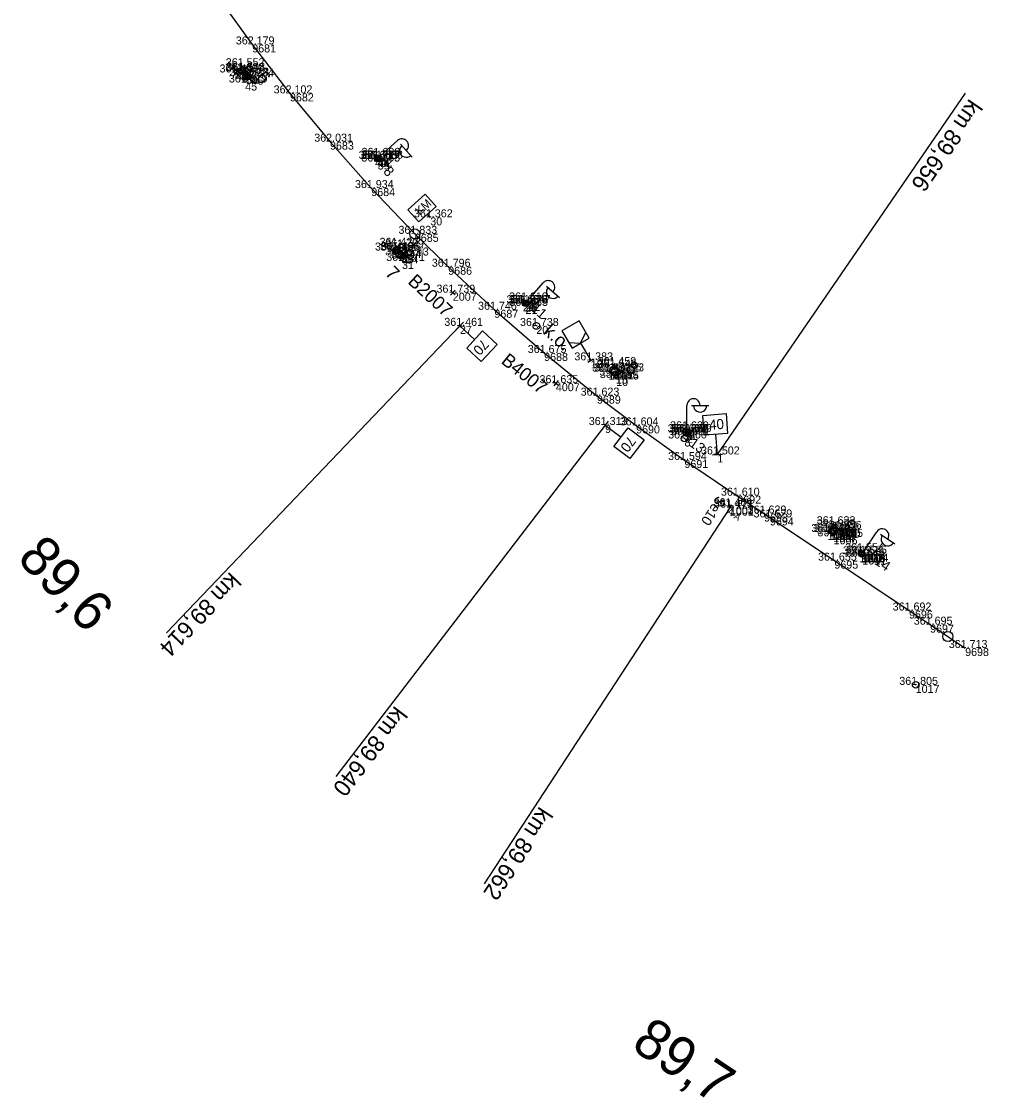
# Model space of a CAD drawing. Extents: x -599511 to -595511, y -1067427 to -1062061.
# Drawn here: x -595656.1 to -595511.1, y -1067426.6 to -1067265.2 of the extents above; entities that cross this region are included whole.
import ezdxf

# ---------------------------------------------------------------- set-up
doc = ezdxf.new("R2010")
doc.units = 0
for name, color, linetype in [('Vrstva 1', 7, 'Continuous'), ('Vrstva 11', 7, 'Continuous'), ('Vrstva 12', 7, 'Continuous'), ('Vrstva 23', 7, 'Continuous'), ('Vrstva 25', 7, 'Continuous'), ('Vrstva 27', 7, 'Continuous'), ('Vrstva 49', 7, 'Continuous'), ('Vrstva 5', 7, 'Continuous'), ('Vrstva 50', 7, 'Continuous'), ('Vrstva 6', 7, 'Continuous'), ('Vrstva 60', 7, 'Continuous'), ('Vrstva 61', 7, 'Continuous'), ('Vrstva 7', 7, 'Continuous')]:
    doc.layers.add(name, color=color, linetype=linetype)

msp = doc.modelspace()

# ---------------------------------------------------------------- linework, layer by layer
at = {"layer": 'Vrstva 1'}
msp.add_lwpolyline([(-595627.48, -1067260.3), (-595621.49, -1067268.64), (-595615.83, -1067275.98), (-595609.83, -1067283.22), (-595603.64, -1067290.18), (-595597.11, -1067297.04), (-595592.1, -1067301.98), (-595585.18, -1067308.43), (-595577.72, -1067314.91), (-595569.8, -1067321.31), (-595563.93, -1067325.77), (-595556.69, -1067330.96), (-595548.76, -1067336.31), (-595544.74, -1067338.99), (-595543.87, -1067339.57), (-595534.2, -1067346.05), (-595523.01, -1067353.53), (-595519.85, -1067355.65), (-595514.6, -1067359.15)], dxfattribs=at)
at = {"layer": 'Vrstva 11'}
for p, q in [((-595623.57, -1067272.76), (-595622.65, -1067272.87)), ((-595623.52, -1067272.39), (-595622.61, -1067272.5)), ((-595622.94, -1067273.51), (-595622.02, -1067273.63)), ((-595622.88, -1067273.14), (-595621.97, -1067273.26)), ((-595600.28, -1067299.72), (-595599.36, -1067299.74)), ((-595600.27, -1067299.35), (-595599.35, -1067299.37)), ((-595599.56, -1067300.08), (-595598.65, -1067300.07)), ((-595599.57, -1067300.45), (-595598.64, -1067300.45)), ((-595567.8, -1067317.77), (-595566.41, -1067317.58)), ((-595567.48, -1067317.35), (-595566.83, -1067317.26)), ((-595567.39, -1067318.09), (-595566.72, -1067318)), ((-595535.07, -1067341.7), (-595533.68, -1067341.43)), ((-595534.77, -1067341.26), (-595534.12, -1067341.14)), ((-595534.63, -1067342), (-595533.97, -1067341.87))]:
    msp.add_line(p, q, dxfattribs=at)
for points in [[(-595567.2, -1067316.97), (-595566.4, -1067317.58), (-595567.01, -1067318.38), (-595567.8, -1067317.77)], [(-595534.51, -1067340.88), (-595533.68, -1067341.43), (-595534.24, -1067342.26), (-595535.07, -1067341.71)]]:
    msp.add_lwpolyline(points, close=True, dxfattribs=at)
for centre in [(-595623.09, -1067272.64), (-595622.45, -1067273.39), (-595599.82, -1067299.55), (-595599.11, -1067300.27)]:
    msp.add_circle(centre, 0.5, dxfattribs=at)
at = {"layer": 'Vrstva 12'}
for p, q in [((-595535.21, -1067341.75), (-595534.4, -1067340.59)), ((-595534.31, -1067342.4), (-595535.21, -1067341.75)), ((-595534.4, -1067340.59), (-595533.48, -1067341.29)), ((-595533.48, -1067341.29), (-595534.31, -1067342.4)), ((-595530.47, -1067345.1), (-595530.14, -1067344.64)), ((-595530.01, -1067345.44), (-595530.47, -1067345.1)), ((-595530.14, -1067344.64), (-595529.69, -1067345.01)), ((-595529.69, -1067345.01), (-595530.01, -1067345.44))]:
    msp.add_line(p, q, dxfattribs=at)
for points in [[(-595623.94, -1067272.84), (-595623.01, -1067271.91), (-595621.6, -1067273.48), (-595622.55, -1067274.35)], [(-595602.65, -1067285.35), (-595603.08, -1067285.8), (-595602.67, -1067286.2), (-595602.26, -1067285.76)], [(-595600.63, -1067299.55), (-595599.94, -1067298.84), (-595598.38, -1067300.29), (-595599.04, -1067301.11)], [(-595580.53, -1067307.03), (-595580.09, -1067307.41), (-595580.5, -1067307.85), (-595580.92, -1067307.45)], [(-595568.08, -1067317.7), (-595567.26, -1067316.71), (-595566.1, -1067317.65), (-595566.92, -1067318.67)], [(-595556.74, -1067326.79), (-595556.37, -1067326.36), (-595555.95, -1067326.76), (-595556.3, -1067327.17)]]:
    msp.add_lwpolyline(points, close=True, dxfattribs=at)
at = {"layer": 'Vrstva 23'}
for p, q in [((-595534.85, -1067341.74), (-595534.39, -1067341.06)), ((-595534.36, -1067342.07), (-595534.85, -1067341.74)), ((-595534.39, -1067341.06), (-595533.88, -1067341.39)), ((-595533.88, -1067341.39), (-595534.36, -1067342.07))]:
    msp.add_line(p, q, dxfattribs=at)
msp.add_lwpolyline([(-595567.22, -1067317.09), (-595566.45, -1067317.67), (-595566.98, -1067318.31), (-595567.73, -1067317.68)], close=True, dxfattribs=at)
at = {"layer": 'Vrstva 25'}
for p, q in [((-595602.32, -1067285.38), (-595599.71, -1067283.05)), ((-595599.24, -1067283.58), (-595597.52, -1067285.52)), ((-595603.12, -1067285.45), (-595602.25, -1067285.5)), ((-595603.18, -1067285.82), (-595602.23, -1067285.88)), ((-595580.18, -1067307.05), (-595577.89, -1067304.41)), ((-595577.36, -1067304.87), (-595575.4, -1067306.57)), ((-595580.98, -1067307.6), (-595580.02, -1067307.53)), ((-595580.97, -1067307.22), (-595580.09, -1067307.16)), ((-595556.35, -1067326.27), (-595556.33, -1067322.77)), ((-595555.63, -1067322.77), (-595553.03, -1067322.79)), ((-595556.83, -1067326.91), (-595556.21, -1067326.29)), ((-595556.6, -1067327.2), (-595555.92, -1067326.53)), ((-595529.81, -1067344.62), (-595527.86, -1067341.71)), ((-595527.28, -1067342.1), (-595525.12, -1067343.54)), ((-595530.56, -1067344.89), (-595529.7, -1067344.72)), ((-595530.53, -1067345.27), (-595529.59, -1067345.08))]:
    msp.add_line(p, q, dxfattribs=at)
for centre in [(-595602.7, -1067285.71), (-595580.51, -1067307.43), (-595556.35, -1067326.76), (-595530.08, -1067345.04)]:
    msp.add_circle(centre, 0.5, dxfattribs=at)
for centre, start, end in [((-595599.04, -1067283.8), 311.633, 131.633), ((-595598.39, -1067284.56), 130.9305, 312.3356), ((-595577.13, -1067305.06), 319.0231, 139.0231), ((-595576.39, -1067305.73), 138.3205, 319.7256), ((-595555.33, -1067322.77), 359.6536, 179.6536), ((-595554.33, -1067322.79), 178.951, 0.3562), ((-595527.03, -1067342.27), 326.2332, 146.2332), ((-595526.2, -1067342.83), 145.5306, 326.9358)]:
    msp.add_arc(centre, 1, start, end, dxfattribs=at)
at = {"layer": 'Vrstva 27'}
msp.add_line((-595578.93, -1067310.83), (-595578.85, -1067310.89), dxfattribs=at)
msp.add_circle((-595578.89, -1067310.86), 0.5, dxfattribs=at)
at = {"layer": 'Vrstva 49'}
for p, q in [((-595623.16, -1067272.54), (-595622.66, -1067272.6)), ((-595622.88, -1067272.32), (-595622.94, -1067272.82)), ((-595622.55, -1067273.3), (-595622.05, -1067273.37)), ((-595622.27, -1067273.09), (-595622.33, -1067273.58)), ((-595602.72, -1067285.57), (-595602.75, -1067286.07)), ((-595602.98, -1067285.8), (-595602.48, -1067285.83)), ((-595599.97, -1067299.46), (-595599.47, -1067299.46)), ((-595599.72, -1067299.21), (-595599.72, -1067299.71)), ((-595599.28, -1067300.16), (-595598.78, -1067300.16)), ((-595599.03, -1067299.91), (-595599.03, -1067300.41)), ((-595580.82, -1067307.53), (-595580.32, -1067307.5)), ((-595580.59, -1067307.26), (-595580.55, -1067307.76)), ((-595556.66, -1067326.89), (-595556.17, -1067326.81)), ((-595556.45, -1067326.6), (-595556.37, -1067327.09)), ((-595550.11, -1067337.93), (-595549.62, -1067337.84)), ((-595549.92, -1067337.64), (-595549.82, -1067338.13)), ((-595530.38, -1067345.18), (-595529.89, -1067345.08)), ((-595530.18, -1067344.88), (-595530.09, -1067345.37))]:
    msp.add_line(p, q, dxfattribs=at)
at = {"layer": 'Vrstva 5'}
for p, q in [((-595551.75, -1067330.12), (-595514.53, -1067275.94)), ((-595590.34, -1067310.84), (-595634.35, -1067356.9)), ((-595589.83, -1067310.29), (-595590.85, -1067311.39)), ((-595590.34, -1067310.84), (-595588.14, -1067312.89)), ((-595568.58, -1067325.71), (-595608.94, -1067378.44)), ((-595568.12, -1067325.12), (-595569.03, -1067326.31)), ((-595568.58, -1067325.71), (-595566.19, -1067327.53)), ((-595551.75, -1067330.12), (-595551.97, -1067327.12)), ((-595552.5, -1067330.17), (-595551, -1067330.06))]:
    msp.add_line(p, q, dxfattribs=at)
for points in [[(-595589.33, -1067314.17), (-595586.95, -1067311.61), (-595584.75, -1067313.65), (-595587.14, -1067316.21)], [(-595550.22, -1067327), (-595553.72, -1067327.25), (-595553.94, -1067324.26), (-595550.45, -1067324)], [(-595567.25, -1067328.92), (-595565.13, -1067326.14), (-595562.74, -1067327.95), (-595564.86, -1067330.74)]]:
    msp.add_lwpolyline(points, close=True, dxfattribs=at)
at = {"layer": 'Vrstva 50'}
msp.add_line((-595556.72, -1067327.7), (-595556.64, -1067327.76), dxfattribs=at)
msp.add_circle((-595556.68, -1067327.73), 0.5, dxfattribs=at)
at = {"layer": 'Vrstva 6'}
for p, q in [((-595549.87, -1067338.11), (-595586.71, -1067394.51)), ((-595550.15, -1067338.53), (-595549.59, -1067337.7))]:
    msp.add_line(p, q, dxfattribs=at)
at = {"layer": 'Vrstva 60'}
for p, q in [((-595621.49, -1067268.64), (-595621.49, -1067268.64)), ((-595623.09, -1067272.64), (-595623.09, -1067272.64)), ((-595623.01, -1067271.91), (-595623.01, -1067271.91)), ((-595622.91, -1067272.57), (-595622.91, -1067272.57)), ((-595623.94, -1067272.84), (-595623.94, -1067272.84)), ((-595622.55, -1067274.35), (-595622.55, -1067274.35)), ((-595622.45, -1067273.39), (-595622.45, -1067273.39)), ((-595622.3, -1067273.33), (-595622.3, -1067273.33)), ((-595621.6, -1067273.48), (-595621.6, -1067273.48)), ((-595615.83, -1067275.98), (-595615.83, -1067275.98)), ((-595609.83, -1067283.22), (-595609.83, -1067283.22)), ((-595602.7, -1067285.71), (-595602.7, -1067285.71)), ((-595602.65, -1067285.35), (-595602.65, -1067285.35)), ((-595603.08, -1067285.8), (-595603.08, -1067285.8)), ((-595602.73, -1067285.82), (-595602.73, -1067285.82)), ((-595602.67, -1067286.2), (-595602.67, -1067286.2)), ((-595602.26, -1067285.76), (-595602.26, -1067285.76)), ((-595603.64, -1067290.18), (-595603.64, -1067290.18)), ((-595594.79, -1067294.57), (-595594.79, -1067294.57)), ((-595597.11, -1067297.04), (-595597.11, -1067297.04)), ((-595600.63, -1067299.55), (-595600.63, -1067299.55)), ((-595599.94, -1067298.84), (-595599.94, -1067298.84)), ((-595599.82, -1067299.55), (-595599.82, -1067299.55)), ((-595599.72, -1067299.46), (-595599.72, -1067299.46)), ((-595599.11, -1067299.08), (-595599.11, -1067299.08)), ((-595599.03, -1067300.16), (-595599.03, -1067300.16)), ((-595599.11, -1067300.27), (-595599.11, -1067300.27)), ((-595599.04, -1067301.11), (-595599.04, -1067301.11)), ((-595598.38, -1067300.29), (-595598.38, -1067300.29)), ((-595592.1, -1067301.98), (-595592.1, -1067301.98)), ((-595591.41, -1067305.87), (-595591.41, -1067305.87)), ((-595580.92, -1067307.45), (-595580.92, -1067307.45)), ((-595580.57, -1067307.51), (-595580.57, -1067307.51)), ((-595580.53, -1067307.03), (-595580.53, -1067307.03)), ((-595580.51, -1067307.43), (-595580.51, -1067307.43)), ((-595580.5, -1067307.85), (-595580.5, -1067307.85)), ((-595580.09, -1067307.41), (-595580.09, -1067307.41)), ((-595585.18, -1067308.43), (-595585.18, -1067308.43)), ((-595590.34, -1067310.84), (-595590.34, -1067310.84)), ((-595578.89, -1067310.86), (-595578.89, -1067310.86)), ((-595577.72, -1067314.91), (-595577.72, -1067314.91)), ((-595570.74, -1067316.02), (-595570.74, -1067316.02)), ((-595568.08, -1067317.7), (-595568.08, -1067317.7)), ((-595567.73, -1067317.68), (-595567.73, -1067317.68)), ((-595567.26, -1067316.71), (-595567.26, -1067316.71)), ((-595567.22, -1067317.09), (-595567.22, -1067317.09)), ((-595567.1, -1067317.68), (-595567.1, -1067317.68)), ((-595566.45, -1067317.67), (-595566.45, -1067317.67)), ((-595566.1, -1067317.65), (-595566.1, -1067317.65)), ((-595575.96, -1067319.44), (-595575.96, -1067319.44)), ((-595566.98, -1067318.31), (-595566.98, -1067318.31)), ((-595566.92, -1067318.67), (-595566.92, -1067318.67)), ((-595569.8, -1067321.31), (-595569.8, -1067321.31)), ((-595568.58, -1067325.71), (-595568.58, -1067325.71)), ((-595563.93, -1067325.77), (-595563.93, -1067325.77)), ((-595556.74, -1067326.79), (-595556.74, -1067326.79)), ((-595556.41, -1067326.85), (-595556.41, -1067326.85)), ((-595556.37, -1067326.36), (-595556.37, -1067326.36)), ((-595556.35, -1067326.76), (-595556.35, -1067326.76)), ((-595556.3, -1067327.17), (-595556.3, -1067327.17)), ((-595555.95, -1067326.76), (-595555.95, -1067326.76)), ((-595556.68, -1067327.73), (-595556.68, -1067327.73)), ((-595551.75, -1067330.12), (-595551.75, -1067330.12)), ((-595556.69, -1067330.96), (-595556.69, -1067330.96)), ((-595548.76, -1067336.31), (-595548.76, -1067336.31)), ((-595549.87, -1067337.89), (-595549.87, -1067337.89)), ((-595549.87, -1067338.11), (-595549.87, -1067338.11)), ((-595544.74, -1067338.99), (-595544.74, -1067338.99)), ((-595543.87, -1067339.57), (-595543.87, -1067339.57)), ((-595535.21, -1067341.75), (-595535.21, -1067341.75)), ((-595534.85, -1067341.74), (-595534.85, -1067341.74)), ((-595534.4, -1067340.59), (-595534.4, -1067340.59)), ((-595534.39, -1067341.06), (-595534.39, -1067341.06)), ((-595534.37, -1067341.57), (-595534.37, -1067341.57)), ((-595534.36, -1067342.07), (-595534.36, -1067342.07)), ((-595533.88, -1067341.39), (-595533.88, -1067341.39)), ((-595533.48, -1067341.29), (-595533.48, -1067341.29)), ((-595534.31, -1067342.4), (-595534.31, -1067342.4)), ((-595530.47, -1067345.1), (-595530.47, -1067345.1)), ((-595530.14, -1067344.64), (-595530.14, -1067344.64)), ((-595530.14, -1067345.13), (-595530.14, -1067345.13)), ((-595530.08, -1067345.04), (-595530.08, -1067345.04)), ((-595529.69, -1067345.01), (-595529.69, -1067345.01)), ((-595534.2, -1067346.05), (-595534.2, -1067346.05)), ((-595530.01, -1067345.44), (-595530.01, -1067345.44)), ((-595523.01, -1067353.53), (-595523.01, -1067353.53)), ((-595519.85, -1067355.65), (-595519.85, -1067355.65)), ((-595514.6, -1067359.15), (-595514.6, -1067359.15)), ((-595522.01, -1067364.68), (-595522.01, -1067364.68))]:
    msp.add_line(p, q, dxfattribs=at)
at = {"layer": 'Vrstva 7'}
for p, q in [((-595594.79, -1067294.57), (-595595.2, -1067294.1)), ((-595599.14, -1067299.05), (-595599.07, -1067299.12)), ((-595591.77, -1067305.53), (-595591.04, -1067306.21)), ((-595591.07, -1067305.5), (-595591.75, -1067306.23)), ((-595572.25, -1067313.43), (-595570.74, -1067316.02)), ((-595571.17, -1067316.27), (-595570.31, -1067315.77)), ((-595576.35, -1067319.13), (-595575.57, -1067319.75)), ((-595575.64, -1067319.05), (-595576.27, -1067319.83)), ((-595522.05, -1067364.65), (-595521.97, -1067364.7))]:
    msp.add_line(p, q, dxfattribs=at)
msp.add_lwpolyline([(-595596.5, -1067295.26), (-595598.16, -1067293.42), (-595595.56, -1067291.09), (-595593.9, -1067292.94)], close=True, dxfattribs=at)
for points in [[(-595572.25, -1067313.43), (-595570.95, -1067312.67), (-595572.46, -1067310.08), (-595575.05, -1067311.59), (-595573.54, -1067314.18), (-595572.25, -1067313.43)], [(-595574.05, -1067313.32), (-595572.25, -1067313.43), (-595571.46, -1067311.81)]]:
    msp.add_lwpolyline(points, dxfattribs=at)
for centre, radius in [((-595597.1, -1067297.05), 0.75), ((-595599.11, -1067299.08), 0.5), ((-595517.19, -1067357.42), 0.75), ((-595522.01, -1067364.68), 0.5)]:
    msp.add_circle(centre, radius, dxfattribs=at)

# ---------------------------------------------------------------- texts
at = {"layer": 'Vrstva 11'}
for s, rotation, p in [('6', 307.6413, (-595621.05, -1067273.58)), ('7', 315.3689, (-595601.68, -1067303.09)), ('8', 322.7429, (-595565.7, -1067317.48)), ('9', 326.2076, (-595532.99, -1067341.29))]:
    msp.add_text(s, height=2, rotation=rotation, dxfattribs=at).set_placement(p)
at = {"layer": 'Vrstva 25'}
for s, rotation, p in [('8', 311.633, (-595601.93, -1067287.77)), ('11', 319.0231, (-595579.8, -1067308.44)), ('13', 324.4159, (-595556.09, -1067328.74)), ('14', 326.2332, (-595528.3, -1067346.48))]:
    msp.add_text(s, height=1.5, rotation=rotation, dxfattribs=at).set_placement(p)
at = {"layer": 'Vrstva 27'}
msp.add_text('k.o.', height=2, rotation=319.0231, dxfattribs=at).set_placement((-595578, -1067311.92))
at = {"layer": 'Vrstva 5'}
for s, height, rotation, p in [('km 89,656', 2.5, 235.5109, (-595513.95, -1067276.67)), ('70', 1.5, 227.0346, (-595586.97, -1067312.73)), ('40', 1.5, 4.2217, (-595552.94, -1067326.44)), ('70', 1.5, 232.7429, (-595565.04, -1067327.26)), ('km 89,614', 2.5, 226.3006, (-595624.81, -1067347.63)), ('km 89,640', 2.5, 232.7429, (-595600.09, -1067367.71))]:
    msp.add_text(s, height=height, rotation=rotation, dxfattribs=at).set_placement(p)
at = {"layer": 'Vrstva 6'}
for s, height, rotation, p in [('Se10', 1.5, 236.2244, (-595551.67, -1067336.23)), ('A A ', 1, 326.2244, (-595550.43, -1067338.94)), ('km 89,662', 2.5, 236.8473, (-595578.41, -1067382.8))]:
    msp.add_text(s, height=height, rotation=rotation, dxfattribs=at).set_placement(p)
at = {"layer": 'Vrstva 60'}
for s, p in [('9681', (-595621.49, -1067269.84)), ('49', (-595623.09, -1067273.84)), ('47', (-595623.01, -1067273.11)), ('52', (-595622.91, -1067273.77)), ('48', (-595623.94, -1067274.04)), ('45', (-595622.55, -1067275.55)), ('50', (-595622.45, -1067274.59)), ('51', (-595622.3, -1067274.53)), ('46', (-595621.6, -1067274.68)), ('9682', (-595615.83, -1067277.18)), ('9683', (-595609.83, -1067284.42)), ('43', (-595602.7, -1067286.91)), ('41', (-595602.65, -1067286.55)), ('40', (-595603.08, -1067287)), ('44', (-595602.73, -1067287.02)), ('39', (-595602.67, -1067287.4)), ('42', (-595602.26, -1067286.96)), ('9684', (-595603.64, -1067291.38)), ('30', (-595594.79, -1067295.77)), ('9685', (-595597.11, -1067298.24)), ('32', (-595600.63, -1067300.75)), ('33', (-595599.94, -1067300.04)), ('36', (-595599.82, -1067300.75)), ('1444', (-595599.72, -1067300.66)), ('29', (-595599.11, -1067300.28)), ('38', (-595599.03, -1067301.36)), ('35', (-595599.11, -1067301.47)), ('31', (-595599.04, -1067302.31)), ('34', (-595598.38, -1067301.49)), ('9686', (-595592.1, -1067303.18)), ('2007', (-595591.41, -1067307.07)), ('24', (-595580.92, -1067308.65)), ('26', (-595580.57, -1067308.71)), ('23', (-595580.53, -1067308.23)), ('25', (-595580.51, -1067308.63)), ('21', (-595580.5, -1067309.05)), ('22', (-595580.09, -1067308.61)), ('9687', (-595585.18, -1067309.63)), ('27', (-595590.34, -1067312.04)), ('20', (-595578.89, -1067312.06)), ('9688', (-595577.72, -1067316.11)), ('18', (-595570.74, -1067317.22)), ('13', (-595568.08, -1067318.9)), ('14', (-595567.73, -1067318.88)), ('12', (-595567.26, -1067317.91)), ('17', (-595567.22, -1067318.29)), ('1445', (-595567.1, -1067318.88)), ('16', (-595566.45, -1067318.87)), ('11', (-595566.1, -1067318.84)), ('4007', (-595575.96, -1067320.64)), ('15', (-595566.98, -1067319.51)), ('10', (-595566.92, -1067319.86)), ('9689', (-595569.8, -1067322.51)), ('9', (-595568.58, -1067326.91)), ('9690', (-595563.93, -1067326.97)), ('5', (-595556.74, -1067327.99)), ('4', (-595556.37, -1067327.56)), ('7', (-595556.41, -1067328.05)), ('6', (-595556.35, -1067327.96)), ('2', (-595556.3, -1067328.37)), ('3', (-595555.95, -1067327.96)), ('8', (-595556.68, -1067328.93)), ('1', (-595551.75, -1067331.32)), ('9691', (-595556.69, -1067332.16)), ('9692', (-595548.76, -1067337.51)), ('1002', (-595549.87, -1067339.09)), ('1001', (-595549.87, -1067339.31)), ('9693', (-595544.74, -1067340.19)), ('9694', (-595543.87, -1067340.77)), ('1004', (-595534.4, -1067341.79)), ('1003', (-595535.21, -1067342.95)), ('1008', (-595534.85, -1067342.94)), ('1009', (-595534.39, -1067342.26)), ('1369', (-595534.37, -1067342.77)), ('1007', (-595534.36, -1067343.27)), ('1010', (-595533.88, -1067342.59)), ('1005', (-595533.48, -1067342.49)), ('1006', (-595534.31, -1067343.6)), ('1012', (-595530.47, -1067346.3)), ('1013', (-595530.14, -1067345.84)), ('1016', (-595530.14, -1067346.33)), ('1015', (-595530.08, -1067346.24)), ('1014', (-595529.69, -1067346.21)), ('9695', (-595534.2, -1067347.25)), ('1011', (-595530.01, -1067346.64)), ('9696', (-595523.01, -1067354.73)), ('9697', (-595519.85, -1067356.85)), ('9698', (-595514.6, -1067360.35)), ('1017', (-595522.01, -1067365.88))]:
    msp.add_text(s, height=1.2, dxfattribs=at).set_placement(p)
at = {"layer": 'Vrstva 61'}
for s, p in [('362.179', (-595623.95, -1067268.64)), ('361.552', (-595625.46, -1067271.91)), ('361.457', (-595626.39, -1067272.84)), ('361.600', (-595625.54, -1067272.64)), ('361.548', (-595625.36, -1067272.57)), ('361.523', (-595624.9, -1067273.39)), ('361.548', (-595624.76, -1067273.33)), ('361.584', (-595624.05, -1067273.48)), ('361.519', (-595625, -1067274.35)), ('362.102', (-595618.28, -1067275.98)), ('362.031', (-595612.19, -1067283.22)), ('361.683', (-595605.53, -1067285.8)), ('361.717', (-595605.18, -1067285.82)), ('361.717', (-595605.15, -1067285.71)), ('361.663', (-595605.12, -1067286.2)), ('361.680', (-595605.1, -1067285.35)), ('361.668', (-595604.71, -1067285.76)), ('361.934', (-595606.09, -1067290.18)), ('361.362', (-595597.24, -1067294.57)), ('361.833', (-595599.56, -1067297.04)), ('361.459', (-595603.09, -1067299.55)), ('361.422', (-595602.39, -1067298.84)), ('361.466', (-595602.27, -1067299.55)), ('361.466', (-595602.17, -1067299.46)), ('361.789', (-595601.56, -1067299.08)), ('361.570', (-595601.56, -1067300.27)), ('361.564', (-595601.48, -1067300.16)), ('361.471', (-595601.4, -1067301.11)), ('361.443', (-595600.83, -1067300.29)), ('361.796', (-595594.56, -1067301.98)), ('361.739', (-595593.86, -1067305.87)), ('361.634', (-595583.37, -1067307.45)), ('361.676', (-595583.02, -1067307.51)), ('361.610', (-595582.98, -1067307.03)), ('361.676', (-595582.96, -1067307.43)), ('361.635', (-595582.95, -1067307.85)), ('361.647', (-595582.55, -1067307.41)), ('361.746', (-595587.63, -1067308.43)), ('361.461', (-595592.69, -1067310.84)), ('361.738', (-595581.34, -1067310.86)), ('361.675', (-595580.18, -1067314.91)), ('361.383', (-595573.19, -1067316.02)), ('361.459', (-595569.71, -1067316.71)), ('361.546', (-595569.67, -1067317.09)), ('361.433', (-595570.53, -1067317.7)), ('361.550', (-595570.19, -1067317.68)), ('361.558', (-595569.56, -1067317.68)), ('361.550', (-595569.43, -1067318.31)), ('361.453', (-595569.37, -1067318.67)), ('361.566', (-595568.9, -1067317.67)), ('361.483', (-595568.55, -1067317.65)), ('361.635', (-595578.41, -1067319.44)), ('361.623', (-595572.25, -1067321.31)), ('361.313', (-595571.03, -1067325.71)), ('361.604', (-595566.38, -1067325.77)), ('361.618', (-595559.19, -1067326.79)), ('361.672', (-595558.86, -1067326.85)), ('361.629', (-595558.83, -1067326.36)), ('361.668', (-595558.81, -1067326.76)), ('361.621', (-595558.66, -1067327.17)), ('361.639', (-595558.4, -1067326.76)), ('361.560', (-595559.13, -1067327.73)), ('361.502', (-595554.2, -1067330.12)), ('361.594', (-595559.14, -1067330.96)), ('361.610', (-595551.21, -1067336.31)), ('361.469', (-595552.32, -1067337.89)), ('361.471', (-595552.23, -1067338.11)), ('361.629', (-595547.2, -1067338.99)), ('361.629', (-595546.33, -1067339.57)), ('361.649', (-595537.66, -1067341.75)), ('361.674', (-595537.3, -1067341.74)), ('361.633', (-595536.85, -1067340.59)), ('361.675', (-595536.85, -1067341.06)), ('361.665', (-595536.83, -1067341.57)), ('361.670', (-595536.33, -1067341.39)), ('361.586', (-595535.93, -1067341.29)), ('361.656', (-595536.81, -1067342.07)), ('361.632', (-595536.75, -1067342.4)), ('361.554', (-595532.59, -1067344.64)), ('361.545', (-595532.14, -1067345.01)), ('361.655', (-595536.65, -1067346.05)), ('361.556', (-595532.92, -1067345.1)), ('361.575', (-595532.59, -1067345.13)), ('361.575', (-595532.54, -1067345.04)), ('361.545', (-595532.46, -1067345.44)), ('361.692', (-595525.46, -1067353.53)), ('361.695', (-595522.3, -1067355.65)), ('361.713', (-595517.05, -1067359.15)), ('361.805', (-595524.47, -1067364.68))]:
    msp.add_text(s, height=1.2, dxfattribs=at).set_placement(p)
at = {"layer": 'Vrstva 7'}
for s, height, rotation, p in [('KM', 1.247, 41.8954, (-595596.37, -1067294.32)), ('B2007', 2, 317.0346, (-595598.28, -1067304.36)), ('B4007', 2, 321.0637, (-595584.3, -1067316.34)), ('89,6', 6, 313.5886, (-595656.92, -1067345.84)), ('89,7', 6, 326.2848, (-595564.86, -1067419.16))]:
    msp.add_text(s, height=height, rotation=rotation, dxfattribs=at).set_placement(p)

doc.saveas('drawing.dxf')
